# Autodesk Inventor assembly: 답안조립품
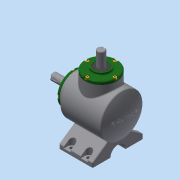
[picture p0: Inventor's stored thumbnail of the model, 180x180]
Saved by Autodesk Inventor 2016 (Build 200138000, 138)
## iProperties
Created: 2017-04
Part Number: 답안조립품
Material: 일반
Document SubType Name: Assembly
Designer: 201-09
Author: 201-09
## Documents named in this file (14)
- C:\Users\201-09\Desktop\470407V1002\답안조립품.iam
- C:\Users\201-09\Desktop\470407V1002\본체.ipt
- C:\Users\201-09\Desktop\470407V1002\메인 베벨기어.ipt
- C:\Users\201-09\Desktop\470407V1002\메인 축.ipt
- 메인 축.ipt
- C:\Users\201-09\Desktop\470407V1002\베어링 6203.ipt
- C:\Users\201-09\Desktop\470407V1002\볼트 M4.ipt
- C:\Users\201-09\Desktop\470407V1002\서브 베벨기어.ipt
- C:\Users\201-09\Desktop\470407V1002\서브 축.ipt
- 서브 축.ipt
- C:\Users\201-09\Desktop\470407V1002\오일실 17 32 8.ipt
- C:\Users\201-09\Desktop\470407V1002\커버.ipt
- C:\Users\201-09\Desktop\470407V1002\키 4x4.ipt
- C:\Users\201-09\Desktop\470407V1002\키 5x5.ipt
